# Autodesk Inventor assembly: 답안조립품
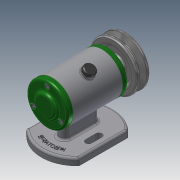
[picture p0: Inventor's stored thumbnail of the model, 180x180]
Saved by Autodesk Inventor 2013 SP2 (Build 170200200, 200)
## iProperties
Created: 2022-02
Part Number: 답안조립품
Document SubType Name: Assembly
Designer: aa
Author: aa
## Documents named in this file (14)
- C:\Users\aa\Desktop\720206V1011\답안조립품.iam
- C:\Users\aa\Desktop\720206V1011\본체.ipt
- C:\Users\aa\Desktop\720206V1011\V벨트풀리.ipt
- C:\Users\aa\Desktop\720206V1011\고무 캡.ipt
- C:\Users\aa\Desktop\720206V1011\너트 M8.ipt
- C:\Users\aa\Desktop\720206V1011\뒤커버.ipt
- C:\Users\aa\Desktop\720206V1011\베어링 6002.ipt
- C:\Users\aa\Desktop\720206V1011\볼트 M4 x 10.ipt
- C:\Users\aa\Desktop\720206V1011\스프링와셔 8.ipt
- C:\Users\aa\Desktop\720206V1011\앞커버.ipt
- C:\Users\aa\Desktop\720206V1011\오일 실 15 x 25 x 7.ipt
- C:\Users\aa\Desktop\720206V1011\축.ipt
- C:\Users\aa\Desktop\720206V1011\키 3 x 3 x 12.ipt
- C:\Users\aa\Desktop\720206V1011\평와셔 8 x 17.ipt
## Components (2 placed, 2 different names)
1. V벨트풀리:1
2. 고무 캡:1
